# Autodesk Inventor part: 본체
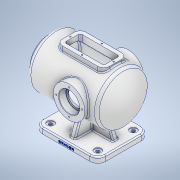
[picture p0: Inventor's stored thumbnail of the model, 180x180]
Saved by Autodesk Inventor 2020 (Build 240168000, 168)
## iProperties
Created: 2021-11
Part Number: 본체
Material: 알루미늄 6061
Document SubType Name: Modeling
Designer: USER
Density: 2.7 g/cm^3
Appearance: 알루미늄 - 평지
Mass: 3545.57 g
Surface Area: 2406.13 cm^2
Volume: 1313.18 cm^3
Author: USER
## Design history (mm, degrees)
sketch "스케치1"
  geometry: L1 (0, 0)-(-160, 0); L2 (-160, 0)-(-160, -130); L3 (-160, -130)-(0, -130); L4 (0, -130)-(0, 0)
  constraints: 8 end point, 2 parallel, 1 horizontal, 1 perpendicular
  dimensions: "d0" = 160 distance of L3.end L2.end; "d1" = 130 distance of L2.end L1.end
extrude "돌출1" new body sketch "스케치1" distance "d2" = 14; taper "d3" = 0 deg
fillet "모깎기1" dims "d4" = 20
sketch "스케치2"
  geometry: A1 r 20 centre (140, 110) between (160, 110) and (140, 130) reference; A2 r 20 centre (140, 20) between (140, 0) and (160, 20) reference; A3 r 20 centre (20, 20) between (0, 20) and (20, 0) reference; A4 r 20 centre (20, 110) between (20, 130) and (0, 110) reference; 5 further points
  constraints: 4 coincident
hole "구멍1" sketch "스케치2" at (140, 110), (140, 20), (20, 20), (20, 110) diameter "d5" = 9; stored, may be unused: countersink angle "d9" = 90 deg, drill point angle "d11" = 118 deg; dims "d6" = 10, "d7" = 18, "d8" = 2, "d10" = 14
fillet "모깎기2" dims "d12" = 3
node "작업 평면1"
sketch "스케치3"
  geometry: L1 (0, 14)-(120, 14) reference; L2 (0, 0)-(-20, 0) reference; L3 (-50, 114)-(160, 114); L4 (-50, 146.5)-(-50, 161.5); L5 (-50, 161.5)-(-40, 161.5); L6 (-40, 161.5)-(-40, 179); L7 (-40, 179)-(135.993, 179); L8 (-50, 146.5)-(-25, 146.5); L9 (-25, 146.5)-(-25, 169); L10 (-25, 169)-(131.239, 169); A1 r 100 centre (60, 114) between (-40, 114) and (135.993, 179); A2 r 90 centre (60, 114) between (-30, 114) and (131.239, 169); 2 further points
  constraints: 16 end point, 5 perpendicular, 4 point on circle, 2 centre point, 2 horizontal, 2 point on line, 1 horizontal alignment, 1 vertical, 1 vertical alignment
  dimensions: "d16" = 210 distance of L3.start L3.end; "d18" = 114 vertical distance of L2.end L3.start; "d19" = 30 horizontal distance of L2.end L3.start; "d20" = 65 diameter of L8 L3; "d21" = 95 diameter of L5 L3; "d22" = 110 diameter of L10 L3; "d23" = 130 diameter of L7 L3; "d24" = 25 distance between parallel lines of L9 L4; "d25" = 10 distance between parallel lines of L4 L6; "d26" = 200 diameter of A1; "d27" = 210 dimension on A1 L4; "d28" = 10 radial gap between concentric circles of A1 A2
revolve "회전1" sketch "스케치3" stored, may be unused: angle "d29" = 90 deg
fillet "모깎기3" dims "d30" = 10
node "작업 평면2"
sketch "스케치4"
  geometry: L1 (-50, 66.5)-(-50, 161.5) reference; C1 r 40 at (77, 114); 2 further points
  constraints: 1 centre point, 1 horizontal alignment, 1 midpoint
  dimensions: "d32" = 80 diameter of C1; "d33" = 127 distance from line of L1 C1.centre
extrude "돌출2" join sketch "스케치4" stored distance "d34" = 14; taper "d35" = 0 deg
node "작업 평면3"
sketch "스케치5"
  geometry: C1 r 40 at (43, 114) reference; C2 r 40 at (43, 114); 1 further point
  constraints: 1 centre point, 1 coincident
  dimensions: "d37" = 80 diameter of C2
extrude "돌출3" join sketch "스케치5" stored distance "d38" = 14; taper "d39" = 0 deg
sketch "스케치6"
  geometry: C1 r 40 at (0, 0) reference; C2 r 21 at (0, 0); 1 further point
  constraints: 1 centre point, 1 coincident
  dimensions: "d40" = 42 diameter of C2
extrude "돌출4" cut sketch "스케치6" extent not by distance; stored distance "d41" = 0; taper "d42" = 0 deg
node "작업 평면4"
sketch "스케치7"
  geometry: L1 (20, -95)-(140, -95); L2 (140, -95)-(140, -35); L3 (140, -35)-(20, -35); L4 (20, -35)-(20, -95); L5 (-30, -112.5)-(-30, -17.5) reference; 3 further points
  constraints: 8 end point, 2 midpoint, 2 parallel, 1 horizontal, 1 horizontal alignment, 1 perpendicular
  dimensions: "d44" = 60 distance between parallel lines of L3 L1; "d45" = 120 distance of L2.end L3.end; "d46" = 50 distance between parallel lines of L5 L4
extrude "돌출5" join sketch "스케치7" stored distance "d47" = 14; taper "d48" = 0 deg
sketch "스케치8"
  geometry: L1 (30, 85)-(130, 85); L2 (130, 85)-(130, 45); L3 (130, 45)-(30, 45); L4 (30, 45)-(30, 85); L5 (20, 95)-(140, 95) reference; L6 (20, 35)-(20, 95) reference; L7 (140, 35)-(20, 35) reference; L8 (140, 95)-(140, 35) reference; 1 further point
  constraints: 8 end point, 2 parallel, 1 horizontal, 1 perpendicular
  dimensions: "d49" = 10 distance between parallel lines of L1 L5; "d50" = 10 distance between parallel lines of L6 L4; "d51" = 10 distance between parallel lines of L7 L3; "d52" = 10 distance between parallel lines of L8 L2
extrude "돌출6" cut sketch "스케치8" distance "d53" = 35.5; taper "d54" = 0 deg
fillet "모깎기4" dims "d55" = 15, "d162" = 5
fillet "모깎기5" dims "d56" = 3
sketch "스케치9"
  geometry: L1 (73, 90)-(87, 90); L2 (87, 90)-(87, 40); L3 (87, 40)-(73, 40); L4 (73, 40)-(73, 90); L5 (0, 110)-(0, 20) reference; L6 (140, 130)-(20, 130) reference; 5 further points
  constraints: 8 end point, 4 midpoint, 2 parallel, 1 horizontal, 1 horizontal alignment, 1 perpendicular, 1 vertical alignment
  dimensions: "d57" = 14 distance of L1.start L1.end; "d58" = 50 distance of L1.end L2.end
extrude "돌출7" join sketch "스케치9" stored distance "d59" = 35.5; taper "d60" = 0 deg
sketch "스케치10"
  geometry: L1 (53, 14)-(53, 54) reference; L2 (-17, 14)-(0, 14) reference; L3 (0, 14)-(16.327, 58.859); 1 further point
  constraints: 2 end point, 1 point on line
  dimensions: "d63" = 53 distance from line of L1 L3.start; "d64" = 110 deg angle of L2 L3
feature "리브1" sketch "스케치10" dims "d65" = 1, "d66" = 14, "d67" = 0, "d68" = 0, "d69" = 1, "d70" = 1
sketch "스케치11"
  geometry: L1 (111, 14)-(129, 14) reference; L2 (106.542, 50.975)-(120, 14); L3 (120, 14)-(137, 14) reference; L4 (67, 14)-(67, 54) reference; 1 further point
  constraints: 2 end point, 1 point on line
  dimensions: "d71" = 53 distance from line of L4 L2.end; "d72" = 110 deg angle of L3 L2
feature "리브2" sketch "스케치11" dims "d73" = 1, "d74" = 14, "d75" = 0, "d76" = 0, "d77" = 1, "d78" = 1
node "작업 평면5"
sketch "스케치12"
  geometry: L1 (-17, 14)-(0, 14) reference; L2 (-5, 14)-(12.196, 61.247); C1 r 55 at (45, 114) reference; 1 further point
  constraints: 2 end point, 1 point on line
  dimensions: "d80" = 50 horizontal distance of C1.centre L2.start; "d81" = 110 deg angle of L1 L2
feature "리브3" sketch "스케치12" dims "d82" = 1, "d83" = 14, "d84" = 0, "d85" = 0, "d86" = 1, "d87" = 1
sketch "스케치13"
  geometry: L1 (81, 14)-(99, 14) reference; L2 (95, 14)-(77.566, 61.899); L3 (90, 14)-(107, 14) reference; C1 r 32.5 at (45, 114) reference; 1 further point
  constraints: 2 end point, 1 point on line
  dimensions: "d88" = 50 horizontal distance of L2.start C1.centre; "d89" = 110 deg angle of L3 L2
feature "리브4" sketch "스케치13" dims "d90" = 1, "d91" = 14, "d92" = 0, "d93" = 0, "d94" = 1, "d95" = 1
fillet "모깎기6" dims "d96" = 3
fillet "모깎기7" dims "d97" = 3
chamfer "모따기1" distance "d98" = 1; stored, may be unused: second distance "d99" = 2, angle "d100" = 45 deg
fillet "모깎기8" dims "d101" = 3
sketch "스케치14"
  geometry: L1 (-30, 17.5)-(-30, 112.5) reference; L2 (137, 140)-(57, 140) reference; L3 (20, 50)-(20, 80) reference; L4 (140, 80)-(140, 50) reference; L5 (35, 95)-(125, 95) reference; 6 further points
  constraints: 2 horizontal alignment, 1 midpoint, 1 vertical alignment
  dimensions: "d102" = 50 distance of point (80, 40) point (80, 90); "d103" = 5 distance from line of L3 point (25, 65); "d104" = 5 distance from line of L4 point (135, 65); "d105" = 55 horizontal distance of point (25, 65) point (80, 90); "d106" = 5 distance from line of point (80, 90) L5
hole "구멍2" sketch "스케치14" at (80, 90), (80, 40), (135, 65), (25, 65) diameter "d107" = 3.242; stored, may be unused: countersink angle "d111" = 90 deg, drill point angle "d113" = 118 deg; dims "d108" = 9, "d109" = 18, "d110" = 2, "d112" = 11
sketch "스케치15"
  geometry: C1 r 22 at (0, 0) reference; C2 r 26 at (0, 0); 1 further point
  constraints: 1 centre point, 1 coincident
  dimensions: "d115" = 52 diameter of C2
extrude "돌출8" cut sketch "스케치15" distance "d116" = 18; taper "d117" = 0 deg
sketch "스케치16"
  geometry: C1 r 40 at (0, 0) reference; C2 r 26 at (0, 0); 1 further point
  constraints: 1 centre point, 1 coincident
  dimensions: "d118" = 52 diameter of C2
extrude "돌출9" cut sketch "스케치16" distance "d119" = 18; taper "d120" = 0 deg
sketch "스케치17"
  geometry: C1 r 21 at (0, 0) reference; 2 further points
  constraints: 1 vertical alignment
  dimensions: "d121" = 32.5 distance of C1.centre point (0, 32.5)
hole "구멍3" sketch "스케치17" at (0, 32.5) diameter "d122" = 3.242; stored, may be unused: countersink angle "d126" = 90 deg, drill point angle "d128" = 118 deg; dims "d123" = 11, "d124" = 4, "d125" = 2, "d127" = 13
sketch "스케치18"
  geometry: C1 r 40 at (0, 0) reference; 2 further points
  constraints: 1 vertical alignment
  dimensions: "d132" = 32.5 distance of C1.centre point (0, 32.5)
hole "구멍4" sketch "스케치18" at (0, 32.5) diameter "d133" = 3.242; stored, may be unused: countersink angle "d137" = 90 deg, drill point angle "d139" = 118 deg; dims "d134" = 11, "d135" = 4, "d136" = 2, "d138" = 13
sketch "스케치19"
  geometry: C1 r 47.5 at (0, 0) reference; 2 further points
  constraints: 1 vertical alignment
  dimensions: "d143" = 40 distance of C1.centre point (0, 40)
hole "구멍5" sketch "스케치19" at (0, 40) diameter "d144" = 3.242; stored, may be unused: countersink angle "d148" = 90 deg, drill point angle "d150" = 118 deg; dims "d145" = 11, "d146" = 4, "d147" = 2, "d149" = 13
chamfer "모따기2" distance "d154" = 1; stored, may be unused: second distance "d155" = 2, angle "d156" = 45 deg
fillet "모깎기9" dims "d157" = 0.3
fillet "모깎기10" dims "d158" = 3
sketch "스케치20"
  geometry: L1 (0, 0)-(120, 0) reference; L2 (120, 14)-(0, 14) reference; 3 further points
  constraints: 1 midpoint, 1 vertical alignment, 1 other
  dimensions: "d159" = 5 distance from line of L1 point (60, 5)
feature "엠보싱1" sketch "스케치20" dims "d160" = 0.5, "d161" = 0
node "솔리드1"
pattern_circular "원형 패턴1" dims angle "d130" = 360 deg
pattern_circular "원형 패턴2" dims angle "d141" = 360 deg
pattern_circular "원형 패턴3" dims angle "d152" = 360 deg
feature "A9D066F2-1C7D-4E18-AEED-F7BC21143FA4" dims "d5" = 9, "d6" = 10, "d7" = 18, "d8" = 2, "d9" = 90 deg, "d10" = 14, "d11" = 118 deg
other parameters: "d13" = -65, "d43" = -184
